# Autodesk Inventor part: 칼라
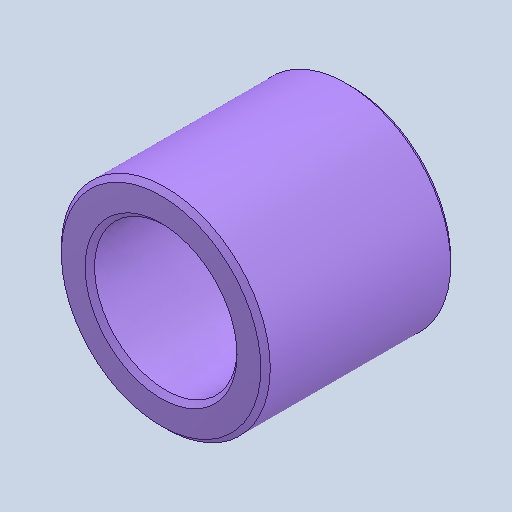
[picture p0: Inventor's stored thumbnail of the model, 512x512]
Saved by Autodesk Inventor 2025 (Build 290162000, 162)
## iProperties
Created: 2024-07
Part Number: 칼라
Material: 스테인리스강
Document SubType Name: Modeling
Designer: samsung
Density: 8.08 g/cm^3
Appearance: 기본값
Author: jhkim
Sending System: Autodesk Inventor 2025
Preprocessor: ST-DEVELOPER v20
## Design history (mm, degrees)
feature "솔리드1"
node "솔리드2"
